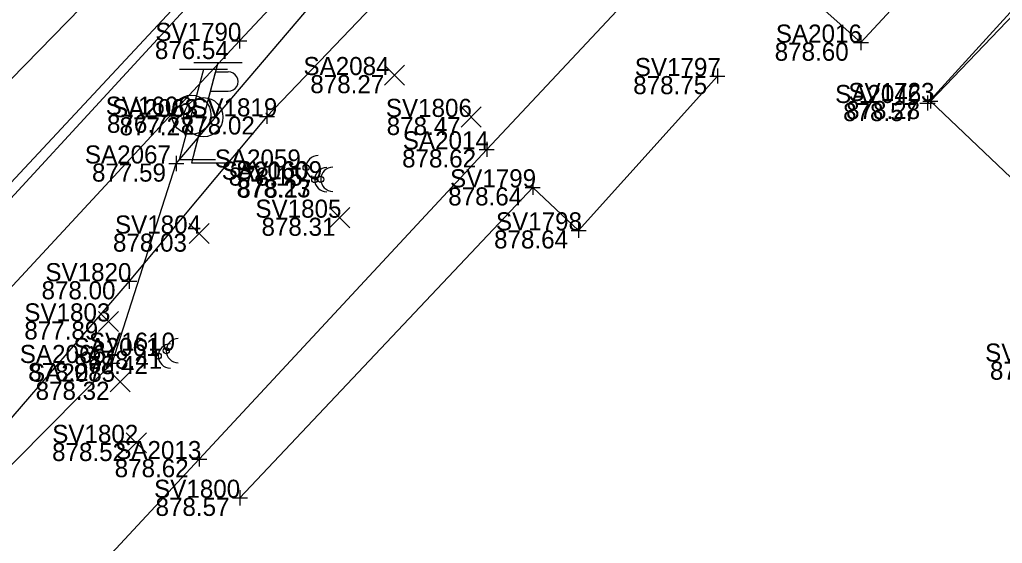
# Model space of a CAD drawing. Extents: x 1480001 to 1480402, y 379235 to 379603.
# Drawn here: x 1480114.4 to 1480179.6, y 379312.6 to 379347.3 of the extents above; entities that cross this region are included whole.
import ezdxf

# ---------------------------------------------------------------- set-up
doc = ezdxf.new("R2010")
doc.units = 0
for name, color, linetype in [('BD_X_Building', 7, 'Continuous'), ('LT_X_Poles', 7, 'Continuous'), ('PV_X_Curb', 7, 'Continuous'), ('PV_X_Walk', 7, 'Continuous'), ('SV_X_Break_Lines', 7, 'Continuous'), ('SV_X_Random_Point', 7, 'Continuous'), ('SV_X_Shot_Marker', 7, 'Continuous'), ('SV_X_Text_Elevation', 7, 'Continuous'), ('SV_X_Text_Name', 7, 'Continuous'), ('UT_X_Misc_Cells', 7, 'Continuous'), ('UT_X_Water', 7, 'Continuous'), ('VG_X_Flower_Bed', 7, 'Continuous')]:
    doc.layers.add(name, color=color, linetype=linetype)

msp = doc.modelspace()

# ---------------------------------------------------------------- linework, layer by layer
at = {"layer": 'BD_X_Building'}
msp.add_lwpolyline([(1480160.694, 379343.603), (1480151.489, 379333.371), (1480148.445, 379336.223), (1480129.012, 379315.639)], dxfattribs=at)
at = {"layer": 'LT_X_Poles'}
msp.add_lwpolyline([(1480127.373, 379343.83), (1480125.798, 379337.845), (1480128.161, 379337.845)], dxfattribs=at)
msp.add_circle((1480126.586, 379340.876), 1.3, dxfattribs=at)
at = {"layer": 'PV_X_Curb'}
for points in [[(1480155.238, 379379.795), (1480153.548, 379379.014), (1480146.824, 379371.927), (1480145.567, 379370.605), (1480143.964, 379368.78), (1480128.12, 379351.892), (1480112.56, 379335.214), (1480098.785, 379320.255), (1480094.793, 379316.092), (1480093.124, 379314.172), (1480085.166, 379305.624), (1480081.585, 379301.702), (1480079.854, 379299.882), (1480067.172, 379286.11), (1480056.531, 379274.485), (1480055.169, 379272.969)], [(1480155.431, 379379.884), (1480153.98, 379378.667), (1480147.216, 379371.505), (1480146.047, 379370.27), (1480144.119, 379368.047), (1480128.647, 379351.629), (1480112.741, 379334.357), (1480099.146, 379319.858), (1480095.569, 379316.008), (1480093.53, 379313.846), (1480085.356, 379305.01), (1480081.967, 379301.397), (1480080.218, 379299.413), (1480067.589, 379285.613), (1480056.688, 379273.774), (1480055.547, 379272.623)]]:
    msp.add_lwpolyline(points, dxfattribs=at)
at = {"layer": 'PV_X_Walk'}
for points in [[(1480059.793, 379271.54), (1480075.261, 379288.048), (1480088.444, 379302.419), (1480096.088, 379310.695), (1480098.33, 379313.163), (1480111.975, 379327.613), (1480128.977, 379345.933), (1480145.46, 379363.52), (1480153.413, 379372.021), (1480155.772, 379374.786), (1480158.213, 379377.107), (1480160.137, 379378.801), (1480161.631, 379379.994)], [(1480108.223, 379298.793), (1480126.311, 379318.205), (1480145.385, 379338.742), (1480160.312, 379354.639), (1480170.225, 379345.82), (1480179.011, 379355.326), (1480188.24, 379365.647)], [(1480192.517, 379361.591), (1480182.642, 379350.612), (1480174.641, 379341.817)]]:
    msp.add_lwpolyline(points, dxfattribs=at)
at = {"layer": 'SV_X_Break_Lines'}
for points in [[(1480109.136, 379300.654), (1480103.503, 379307.396), (1480120.541, 379324.578), (1480124.787, 379337.805), (1480137.007, 379352.173), (1480144.932, 379357.565), (1480149.611, 379361.971), (1480150.052, 379364.189), (1480148.777, 379365.458), (1480163.875, 379379.601), (1480168.818, 379380.654), (1480172.802, 379381.332), (1480178.472, 379378.317), (1480184.655, 379372.421), (1480187.645, 379366.317)], [(1480184.481, 379363.392), (1480180.224, 379367.084), (1480176.21, 379371.695), (1480171.222, 379375.535), (1480168.077, 379375.239), (1480160.326, 379371.415), (1480150.91, 379361.854), (1480140.301, 379350.86), (1480130.798, 379340.93), (1480121.664, 379330.001), (1480112.679, 379319.616)]]:
    msp.add_lwpolyline(points, dxfattribs=at)
at = {"layer": 'SV_X_Random_Point'}
for p, q in [((1480138.598, 379343.001), (1480139.931, 379344.336)), ((1480138.598, 379344.336), (1480139.931, 379343.001)), ((1480143.696, 379340.226), (1480145.03, 379341.561)), ((1480143.696, 379341.561), (1480145.03, 379340.226)), ((1480134.963, 379333.544), (1480136.297, 379334.879)), ((1480134.963, 379334.879), (1480136.297, 379333.544)), ((1480125.635, 379332.493), (1480126.969, 379333.828)), ((1480125.635, 379333.828), (1480126.969, 379332.493)), ((1480119.628, 379326.667), (1480120.962, 379328.002)), ((1480119.628, 379328.002), (1480120.962, 379326.667)), ((1480120.396, 379322.668), (1480121.729, 379324.003)), ((1480120.396, 379324.003), (1480121.729, 379322.668)), ((1480121.471, 379318.612), (1480122.805, 379319.947)), ((1480121.471, 379319.947), (1480122.805, 379318.612))]:
    msp.add_line(p, q, dxfattribs=at)
at = {"layer": 'SV_X_Shot_Marker'}
for p, q in [((1480128.477, 379345.933), (1480129.477, 379345.933)), ((1480128.977, 379346.433), (1480128.977, 379345.433)), ((1480128.977, 379345.933), (1480128.977, 379345.933)), ((1480169.725, 379345.82), (1480170.725, 379345.82)), ((1480170.225, 379346.32), (1480170.225, 379345.32)), ((1480170.225, 379345.82), (1480170.225, 379345.82)), ((1480160.694, 379344.103), (1480160.694, 379343.103)), ((1480160.194, 379343.603), (1480161.194, 379343.603)), ((1480160.694, 379343.603), (1480160.694, 379343.603)), ((1480174.331, 379341.95), (1480175.331, 379341.95)), ((1480174.641, 379342.317), (1480174.641, 379341.317)), ((1480174.831, 379342.45), (1480174.831, 379341.45)), ((1480174.831, 379341.95), (1480174.831, 379341.95)), ((1480130.798, 379341.43), (1480130.798, 379340.43)), ((1480174.141, 379341.817), (1480175.141, 379341.817)), ((1480174.641, 379341.817), (1480174.641, 379341.817)), ((1480130.298, 379340.93), (1480131.298, 379340.93)), ((1480130.798, 379340.93), (1480130.798, 379340.93)), ((1480144.885, 379338.742), (1480145.885, 379338.742)), ((1480145.385, 379339.242), (1480145.385, 379338.242)), ((1480145.385, 379338.742), (1480145.385, 379338.742)), ((1480124.787, 379338.305), (1480124.787, 379337.305)), ((1480124.287, 379337.805), (1480125.287, 379337.805)), ((1480124.787, 379337.805), (1480124.787, 379337.805)), ((1480148.445, 379336.723), (1480148.445, 379335.723)), ((1480147.945, 379336.223), (1480148.945, 379336.223)), ((1480148.445, 379336.223), (1480148.445, 379336.223)), ((1480151.489, 379333.871), (1480151.489, 379332.871)), ((1480150.989, 379333.371), (1480151.989, 379333.371)), ((1480151.489, 379333.371), (1480151.489, 379333.371)), ((1480121.664, 379330.501), (1480121.664, 379329.501)), ((1480121.164, 379330.001), (1480122.164, 379330.001)), ((1480121.664, 379330.001), (1480121.664, 379330.001)), ((1480120.541, 379325.078), (1480120.541, 379324.078)), ((1480120.041, 379324.578), (1480121.041, 379324.578)), ((1480120.541, 379324.578), (1480120.541, 379324.578)), ((1480126.311, 379318.705), (1480126.311, 379317.705)), ((1480125.811, 379318.205), (1480126.811, 379318.205)), ((1480126.311, 379318.205), (1480126.311, 379318.205)), ((1480129.012, 379316.139), (1480129.012, 379315.139)), ((1480128.512, 379315.639), (1480129.512, 379315.639)), ((1480129.012, 379315.639), (1480129.012, 379315.639))]:
    msp.add_line(p, q, dxfattribs=at)
at = {"layer": 'UT_X_Misc_Cells'}
for p, q in [((1480126.593, 379344.04), (1480124.987, 379338.04)), ((1480128.193, 379344.04), (1480124.993, 379344.04)), ((1480127.549, 379344.476), (1480125.943, 379338.476)), ((1480129.149, 379344.476), (1480125.949, 379344.476)), ((1480127.389, 379343.876), (1480128.239, 379343.876)), ((1480127.048, 379342.601), (1480128.239, 379342.601)), ((1480127.387, 379338.04), (1480124.987, 379338.04))]:
    msp.add_line(p, q, dxfattribs=at)
for centre, radius in [((1480125.79, 379341.04), 1.3), ((1480126.586, 379340.876), 1.3), ((1480133.398, 379337.539), 0.2), ((1480133.972, 379336.732), 0.2), ((1480134.372, 379336.761), 0.2), ((1480124.121, 379325.393), 0.2), ((1480123.593, 379325.041), 0.2)]:
    msp.add_circle(centre, radius, dxfattribs=at)
for centre, radius, start, end in [((1480128.252, 379343.239), 0.638, 268.8767, 91.1233), ((1480134.198, 379337.539), 0.8, 90, 270), ((1480134.772, 379336.732), 0.8, 90, 270), ((1480135.172, 379336.761), 0.8, 90, 270), ((1480124.393, 379325.041), 0.8, 90, 270), ((1480124.921, 379325.393), 0.8, 90, 270)]:
    msp.add_arc(centre, radius, start, end, dxfattribs=at)
at = {"layer": 'UT_X_Water'}
msp.add_lwpolyline([(1480169.204, 379397.823), (1480165.761, 379394.087), (1480162.59, 379391.88), (1480159.156, 379388.706), (1480148.911, 379378.819), (1480120.344, 379350.087), (1480106.297, 379335.736), (1480080.736, 379308.289), (1480073.091, 379299.637), (1480056.748, 379281.628), (1480051.266, 379275.974)], dxfattribs=at)
at = {"layer": 'VG_X_Flower_Bed'}
msp.add_lwpolyline([(1480195.813, 379355.199), (1480193.023, 379354.253), (1480190.027, 379352.057), (1480188.179, 379350.767), (1480186.704, 379350.296), (1480182.933, 379350.411), (1480174.831, 379341.95), (1480185.507, 379331.81), (1480186.83, 379332.732), (1480189.913, 379333.545), (1480194.82, 379332.714), (1480198.902, 379333.057), (1480201.966, 379334.947), (1480204.125, 379337.531), (1480204.97, 379340.165), (1480204.571, 379345.003), (1480203.872, 379349.431), (1480202.983, 379352.861), (1480201.244, 379354.971), (1480198.952, 379355.701), (1480197.886, 379355.471)], dxfattribs=at)

# ---------------------------------------------------------------- texts
at = {"layer": 'SV_X_Text_Elevation'}
for s, p in [('876.54', (1480123.365, 379344.733)), ('878.60', (1480164.5, 379344.62)), ('878.27', (1480133.681, 379342.469)), ('878.75', (1480155.11, 379342.403)), ('878.28', (1480169.238, 379340.75)), ('878.57', (1480169.039, 379340.617)), ('876.77', (1480120.187, 379339.84)), ('877.27', (1480121.021, 379339.676)), ('877.27', (1480121.021, 379339.676)), ('878.02', (1480125.091, 379339.73)), ('878.47', (1480138.751, 379339.694)), ('878.62', (1480139.773, 379337.542)), ('877.59', (1480119.194, 379336.605)), ('878.15', (1480128.268, 379336.339)), ('878.23', (1480128.788, 379335.561)), ('878.17', (1480128.842, 379335.532)), ('878.64', (1480142.833, 379335.023)), ('878.31', (1480130.442, 379333.012)), ('878.03', (1480120.586, 379331.96)), ('878.64', (1480145.877, 379332.171)), ('878.00', (1480115.844, 379328.801)), ('877.89', (1480114.702, 379326.134)), ('878.42', (1480117.99, 379323.841)), ('878.41', (1480118.943, 379324.193)), ('878.27', (1480114.958, 379323.378)), ('878.61', (1480178.784, 379323.469)), ('878.32', (1480115.45, 379322.136)), ('878.52', (1480116.545, 379318.079)), ('878.62', (1480120.699, 379317.005)), ('878.57', (1480123.409, 379314.439))]:
    msp.add_text(s, height=1.2, dxfattribs=at).set_placement(p)
at = {"layer": 'SV_X_Text_Name'}
for s, p in [('SV1790', (1480123.394, 379345.933)), ('SA2016', (1480164.576, 379345.82)), ('SA2084', (1480133.227, 379343.669)), ('SV1797', (1480155.215, 379343.603)), ('SA2046', (1480168.51, 379341.817)), ('SV1723', (1480169.39, 379341.95)), ('SV1606', (1480120.103, 379341.04)), ('SA2063', (1480120.52, 379340.876)), ('SA2062', (1480120.53, 379340.876)), ('SV1819', (1480125.782, 379340.93)), ('SV1806', (1480138.695, 379340.894)), ('SA2014', (1480139.82, 379338.742)), ('SA2067', (1480118.721, 379337.805)), ('SA2059', (1480127.341, 379337.539)), ('SV1609', (1480128.751, 379336.761)), ('SA2060', (1480127.802, 379336.732)), ('SV1799', (1480142.956, 379336.223)), ('SV1805', (1480130.037, 379334.212)), ('SV1804', (1480120.719, 379333.16)), ('SV1798', (1480146, 379333.371)), ('SV1820', (1480116.1, 379330.001)), ('SV1803', (1480114.702, 379327.334)), ('SA2061', (1480117.961, 379325.041)), ('SV1610', (1480118.992, 379325.393)), ('SA2066', (1480114.4, 379324.578)), ('SV1694', (1480178.464, 379324.669)), ('SA2085', (1480115.016, 379323.336)), ('SV1802', (1480116.555, 379319.279)), ('SA2013', (1480120.737, 379318.205)), ('SV1800', (1480123.315, 379315.639))]:
    msp.add_text(s, height=1.2, dxfattribs=at).set_placement(p)

doc.saveas('drawing.dxf')
